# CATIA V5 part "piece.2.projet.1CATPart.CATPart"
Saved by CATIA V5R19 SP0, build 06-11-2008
Part number: piece.2.projet
Bounding box of the stored display mesh (mm): x 0 to 50, y -25 to 100, z -24.818 to 24.818
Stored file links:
  F:\piece.2.projet.1CATPart.CATPart
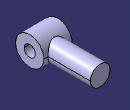
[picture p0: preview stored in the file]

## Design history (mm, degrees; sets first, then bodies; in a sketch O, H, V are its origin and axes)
Parameters
  petitrayon2 = 10 mm
  grandrayon2 = 25 mm
  Longueur_p2 = 50 mm
  demiLongueur2 = 25 mm
Body1 (main body)
  Sketch1 on yz-plane, origin (0, 0, 0), H (0, 1, 0), V (0, 0, 1)
    circle A1 centre (0, 0) radius 25
    radius A1 = 25 {= petitrayon2 *(5/2)}
  Pad1: profile Sketch1, direction (1, 0, 0), length 50 {= Longueur_p2}
  Sketch2 on zx-plane, origin (0, 0, 0), H (-1, 0, 0), V (0, 0, 1)
    circle A1 centre (-25, 0) radius 17.5
    point P1 (-25, 0)
    reference projected line E1 (-50, -25) -> (-50, 25) from edge [face of Pad1 from Sketch1.A1 | end face of Pad1]
    radius A1 = 17.5
    distance P1 E1 = 25 {= Longueur_p2 /2}
    coincidence: P1 H
  Pad2: profile Sketch2, direction (0, 1, 0), length 100
  Sketch3 on end face of Pad1, origin (50, 0, 0), H (0, 1, 0), V (0, 0, 1)
    circle A1 centre (0, 0) radius 10
    radius A1 = 10 {= petitrayon2}
  Pocket1: profile Sketch3, direction (-1, 0, 0), through (limit type 3)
